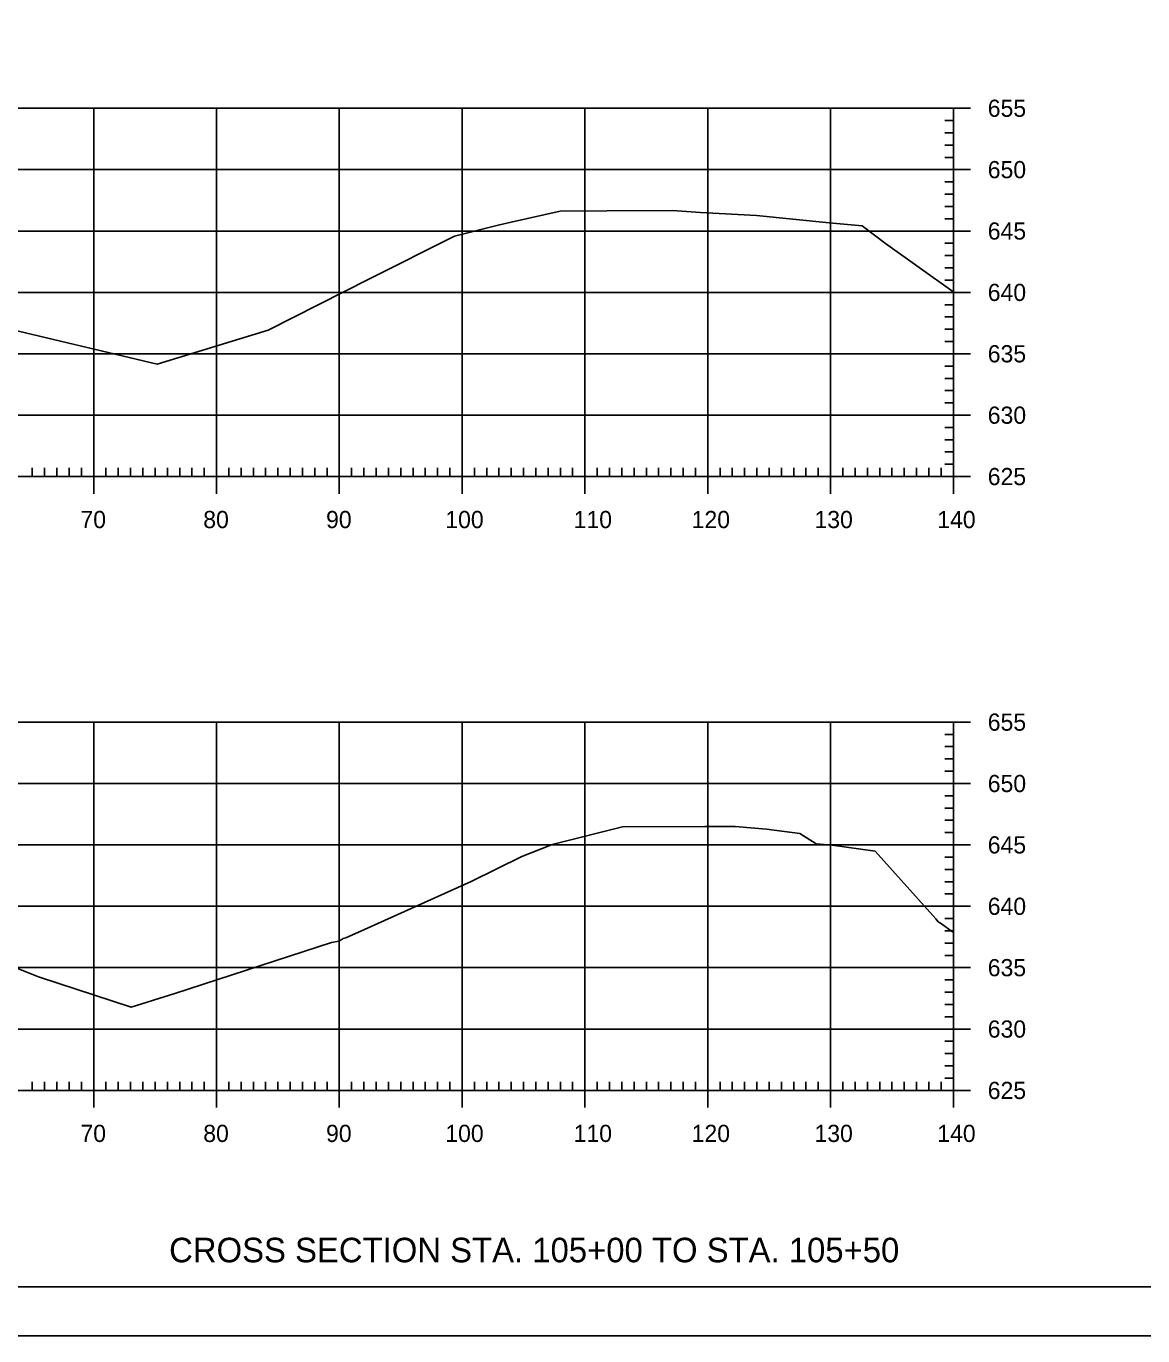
# Model space of a CAD drawing. Extents: x 1381471 to 1382703, y 370300 to 371487.
# Drawn here: x 1382201.1 to 1382292, y 371273.8 to 371380.5 of the extents above; entities that cross this region are included whole.
import ezdxf

# ---------------------------------------------------------------- set-up
doc = ezdxf.new("R2010")
doc.units = 0
doc.layers.add('Level 45', color=7, linetype='Continuous')

msp = doc.modelspace()

# ---------------------------------------------------------------- linework, layer by layer
at = {"layer": 'Level 45'}
for p, q in [((1381996.61, 371373.8), (1382276.61, 371373.8)), ((1382206.61, 371343.8), (1382206.61, 371373.8)), ((1382216.61, 371343.8), (1382216.61, 371373.8)), ((1382226.61, 371343.8), (1382226.61, 371373.8)), ((1382236.61, 371343.8), (1382236.61, 371373.8)), ((1382246.61, 371343.8), (1382246.61, 371373.8)), ((1382256.61, 371343.8), (1382256.61, 371373.8)), ((1382266.61, 371343.8), (1382266.61, 371373.8)), ((1382278.01, 371373.8), (1382275.21, 371373.8)), ((1382276.61, 371372.8), (1382275.91, 371372.8)), ((1382276.61, 371343.8), (1382276.61, 371373.8)), ((1382276.61, 371343.8), (1382276.61, 371373.8)), ((1382276.61, 371371.8), (1382275.91, 371371.8)), ((1382276.61, 371370.8), (1382275.91, 371370.8)), ((1382276.61, 371369.8), (1382275.91, 371369.8)), ((1381996.61, 371368.8), (1382276.61, 371368.8)), ((1382278.01, 371368.8), (1382275.21, 371368.8)), ((1382276.61, 371367.8), (1382275.91, 371367.8)), ((1382276.61, 371366.8), (1382275.91, 371366.8)), ((1382276.61, 371365.8), (1382275.91, 371365.8)), ((1382276.61, 371364.8), (1382275.91, 371364.8)), ((1381996.61, 371363.8), (1382276.61, 371363.8)), ((1382278.01, 371363.8), (1382275.21, 371363.8)), ((1382276.61, 371362.8), (1382275.91, 371362.8)), ((1382276.61, 371361.8), (1382275.91, 371361.8)), ((1382276.61, 371360.8), (1382275.91, 371360.8)), ((1382276.61, 371359.8), (1382275.91, 371359.8)), ((1381996.61, 371358.8), (1382276.61, 371358.8)), ((1382278.01, 371358.8), (1382275.21, 371358.8)), ((1382276.61, 371357.8), (1382275.91, 371357.8)), ((1382276.61, 371356.8), (1382275.91, 371356.8)), ((1382276.61, 371355.8), (1382275.91, 371355.8)), ((1382276.61, 371354.8), (1382275.91, 371354.8)), ((1381996.61, 371353.8), (1382276.61, 371353.8)), ((1382278.01, 371353.8), (1382275.21, 371353.8)), ((1382276.61, 371352.8), (1382275.91, 371352.8)), ((1382276.61, 371351.8), (1382275.91, 371351.8)), ((1382276.61, 371350.8), (1382275.91, 371350.8)), ((1382276.61, 371349.8), (1382275.91, 371349.8)), ((1381996.61, 371348.8), (1382276.61, 371348.8)), ((1382278.01, 371348.8), (1382275.21, 371348.8)), ((1382276.61, 371347.8), (1382275.91, 371347.8)), ((1382276.61, 371346.8), (1382275.91, 371346.8)), ((1382206.61, 371342.4), (1382206.61, 371345.2)), ((1382216.61, 371342.4), (1382216.61, 371345.2)), ((1382226.61, 371342.4), (1382226.61, 371345.2)), ((1382236.61, 371342.4), (1382236.61, 371345.2)), ((1382246.61, 371342.4), (1382246.61, 371345.2)), ((1382256.61, 371342.4), (1382256.61, 371345.2)), ((1382266.61, 371342.4), (1382266.61, 371345.2)), ((1382276.61, 371345.8), (1382275.91, 371345.8)), ((1382276.61, 371342.4), (1382276.61, 371345.2)), ((1382201.61, 371343.8), (1382201.61, 371344.5)), ((1382202.61, 371343.8), (1382202.61, 371344.5)), ((1382203.61, 371343.8), (1382203.61, 371344.5)), ((1382204.61, 371343.8), (1382204.61, 371344.5)), ((1382205.61, 371343.8), (1382205.61, 371344.5)), ((1382207.61, 371343.8), (1382207.61, 371344.5)), ((1382208.61, 371343.8), (1382208.61, 371344.5)), ((1382209.61, 371343.8), (1382209.61, 371344.5)), ((1382210.61, 371343.8), (1382210.61, 371344.5)), ((1382211.61, 371343.8), (1382211.61, 371344.5)), ((1382212.61, 371343.8), (1382212.61, 371344.5)), ((1382213.61, 371343.8), (1382213.61, 371344.5)), ((1382214.61, 371343.8), (1382214.61, 371344.5)), ((1382215.61, 371343.8), (1382215.61, 371344.5)), ((1382217.61, 371343.8), (1382217.61, 371344.5)), ((1382218.61, 371343.8), (1382218.61, 371344.5)), ((1382219.61, 371343.8), (1382219.61, 371344.5)), ((1382220.61, 371343.8), (1382220.61, 371344.5)), ((1382221.61, 371343.8), (1382221.61, 371344.5)), ((1382222.61, 371343.8), (1382222.61, 371344.5)), ((1382223.61, 371343.8), (1382223.61, 371344.5)), ((1382224.61, 371343.8), (1382224.61, 371344.5)), ((1382225.61, 371343.8), (1382225.61, 371344.5)), ((1382227.61, 371343.8), (1382227.61, 371344.5)), ((1382228.61, 371343.8), (1382228.61, 371344.5)), ((1382229.61, 371343.8), (1382229.61, 371344.5)), ((1382230.61, 371343.8), (1382230.61, 371344.5)), ((1382231.61, 371343.8), (1382231.61, 371344.5)), ((1382232.61, 371343.8), (1382232.61, 371344.5)), ((1382233.61, 371343.8), (1382233.61, 371344.5)), ((1382234.61, 371343.8), (1382234.61, 371344.5)), ((1382235.61, 371343.8), (1382235.61, 371344.5)), ((1382237.61, 371343.8), (1382237.61, 371344.5)), ((1382238.61, 371343.8), (1382238.61, 371344.5)), ((1382239.61, 371343.8), (1382239.61, 371344.5)), ((1382240.61, 371343.8), (1382240.61, 371344.5)), ((1382241.61, 371343.8), (1382241.61, 371344.5)), ((1382242.61, 371343.8), (1382242.61, 371344.5)), ((1382243.61, 371343.8), (1382243.61, 371344.5)), ((1382244.61, 371343.8), (1382244.61, 371344.5)), ((1382245.61, 371343.8), (1382245.61, 371344.5)), ((1382247.61, 371343.8), (1382247.61, 371344.5)), ((1382248.61, 371343.8), (1382248.61, 371344.5)), ((1382249.61, 371343.8), (1382249.61, 371344.5)), ((1382250.61, 371343.8), (1382250.61, 371344.5)), ((1382251.61, 371343.8), (1382251.61, 371344.5)), ((1382252.61, 371343.8), (1382252.61, 371344.5)), ((1382253.61, 371343.8), (1382253.61, 371344.5)), ((1382254.61, 371343.8), (1382254.61, 371344.5)), ((1382255.61, 371343.8), (1382255.61, 371344.5)), ((1382257.61, 371343.8), (1382257.61, 371344.5)), ((1382258.61, 371343.8), (1382258.61, 371344.5)), ((1382259.61, 371343.8), (1382259.61, 371344.5)), ((1382260.61, 371343.8), (1382260.61, 371344.5)), ((1382261.61, 371343.8), (1382261.61, 371344.5)), ((1382262.61, 371343.8), (1382262.61, 371344.5)), ((1382263.61, 371343.8), (1382263.61, 371344.5)), ((1382264.61, 371343.8), (1382264.61, 371344.5)), ((1382265.61, 371343.8), (1382265.61, 371344.5)), ((1382267.61, 371343.8), (1382267.61, 371344.5)), ((1382268.61, 371343.8), (1382268.61, 371344.5)), ((1382269.61, 371343.8), (1382269.61, 371344.5)), ((1382270.61, 371343.8), (1382270.61, 371344.5)), ((1382271.61, 371343.8), (1382271.61, 371344.5)), ((1382272.61, 371343.8), (1382272.61, 371344.5)), ((1382273.61, 371343.8), (1382273.61, 371344.5)), ((1382274.61, 371343.8), (1382274.61, 371344.5)), ((1382275.61, 371343.8), (1382275.61, 371344.5)), ((1382276.61, 371344.8), (1382275.91, 371344.8)), ((1381996.61, 371343.8), (1382276.61, 371343.8)), ((1381996.61, 371343.8), (1382276.61, 371343.8)), ((1382278.01, 371343.8), (1382275.21, 371343.8)), ((1381996.61, 371323.8), (1382276.61, 371323.8)), ((1382206.61, 371293.8), (1382206.61, 371323.8)), ((1382216.61, 371293.8), (1382216.61, 371323.8)), ((1382226.61, 371293.8), (1382226.61, 371323.8)), ((1382236.61, 371293.8), (1382236.61, 371323.8)), ((1382246.61, 371293.8), (1382246.61, 371323.8)), ((1382256.61, 371293.8), (1382256.61, 371323.8)), ((1382266.61, 371293.8), (1382266.61, 371323.8)), ((1382278.01, 371323.8), (1382275.21, 371323.8)), ((1382276.61, 371293.8), (1382276.61, 371323.8)), ((1382276.61, 371293.8), (1382276.61, 371323.8)), ((1382276.61, 371322.8), (1382275.91, 371322.8)), ((1382276.61, 371321.8), (1382275.91, 371321.8)), ((1382276.61, 371320.8), (1382275.91, 371320.8)), ((1382276.61, 371319.8), (1382275.91, 371319.8)), ((1381996.61, 371318.8), (1382276.61, 371318.8)), ((1382278.01, 371318.8), (1382275.21, 371318.8)), ((1382276.61, 371317.8), (1382275.91, 371317.8)), ((1382276.61, 371316.8), (1382275.91, 371316.8)), ((1382276.61, 371315.8), (1382275.91, 371315.8)), ((1382276.61, 371314.8), (1382275.91, 371314.8)), ((1381996.61, 371313.8), (1382276.61, 371313.8)), ((1382278.01, 371313.8), (1382275.21, 371313.8)), ((1382276.61, 371312.8), (1382275.91, 371312.8)), ((1382276.61, 371311.8), (1382275.91, 371311.8)), ((1382276.61, 371310.8), (1382275.91, 371310.8)), ((1381996.61, 371308.8), (1382276.61, 371308.8)), ((1382278.01, 371308.8), (1382275.21, 371308.8)), ((1382276.61, 371309.8), (1382275.91, 371309.8)), ((1382276.61, 371307.8), (1382275.91, 371307.8)), ((1382276.61, 371306.8), (1382275.91, 371306.8)), ((1382276.61, 371305.8), (1382275.91, 371305.8)), ((1382276.61, 371304.8), (1382275.91, 371304.8)), ((1381996.61, 371303.8), (1382276.61, 371303.8)), ((1382278.01, 371303.8), (1382275.21, 371303.8)), ((1382276.61, 371302.8), (1382275.91, 371302.8)), ((1382276.61, 371301.8), (1382275.91, 371301.8)), ((1382276.61, 371300.8), (1382275.91, 371300.8)), ((1382276.61, 371299.8), (1382275.91, 371299.8)), ((1381996.61, 371298.8), (1382276.61, 371298.8)), ((1382278.01, 371298.8), (1382275.21, 371298.8)), ((1382276.61, 371297.8), (1382275.91, 371297.8)), ((1382276.61, 371296.8), (1382275.91, 371296.8)), ((1382206.61, 371292.4), (1382206.61, 371295.2)), ((1382216.61, 371292.4), (1382216.61, 371295.2)), ((1382226.61, 371292.4), (1382226.61, 371295.2)), ((1382236.61, 371292.4), (1382236.61, 371295.2)), ((1382246.61, 371292.4), (1382246.61, 371295.2)), ((1382256.61, 371292.4), (1382256.61, 371295.2)), ((1382266.61, 371292.4), (1382266.61, 371295.2)), ((1382276.61, 371295.8), (1382275.91, 371295.8)), ((1382276.61, 371292.4), (1382276.61, 371295.2)), ((1382201.61, 371293.8), (1382201.61, 371294.5)), ((1382202.61, 371293.8), (1382202.61, 371294.5)), ((1382203.61, 371293.8), (1382203.61, 371294.5)), ((1382204.61, 371293.8), (1382204.61, 371294.5)), ((1382205.61, 371293.8), (1382205.61, 371294.5)), ((1382207.61, 371293.8), (1382207.61, 371294.5)), ((1382208.61, 371293.8), (1382208.61, 371294.5)), ((1382209.61, 371293.8), (1382209.61, 371294.5)), ((1382210.61, 371293.8), (1382210.61, 371294.5)), ((1382211.61, 371293.8), (1382211.61, 371294.5)), ((1382212.61, 371293.8), (1382212.61, 371294.5)), ((1382213.61, 371293.8), (1382213.61, 371294.5)), ((1382214.61, 371293.8), (1382214.61, 371294.5)), ((1382215.61, 371293.8), (1382215.61, 371294.5)), ((1382217.61, 371293.8), (1382217.61, 371294.5)), ((1382218.61, 371293.8), (1382218.61, 371294.5)), ((1382219.61, 371293.8), (1382219.61, 371294.5)), ((1382220.61, 371293.8), (1382220.61, 371294.5)), ((1382221.61, 371293.8), (1382221.61, 371294.5)), ((1382222.61, 371293.8), (1382222.61, 371294.5)), ((1382223.61, 371293.8), (1382223.61, 371294.5)), ((1382224.61, 371293.8), (1382224.61, 371294.5)), ((1382225.61, 371293.8), (1382225.61, 371294.5)), ((1382227.61, 371293.8), (1382227.61, 371294.5)), ((1382228.61, 371293.8), (1382228.61, 371294.5)), ((1382229.61, 371293.8), (1382229.61, 371294.5)), ((1382230.61, 371293.8), (1382230.61, 371294.5)), ((1382231.61, 371293.8), (1382231.61, 371294.5)), ((1382232.61, 371293.8), (1382232.61, 371294.5)), ((1382233.61, 371293.8), (1382233.61, 371294.5)), ((1382234.61, 371293.8), (1382234.61, 371294.5)), ((1382235.61, 371293.8), (1382235.61, 371294.5)), ((1382237.61, 371293.8), (1382237.61, 371294.5)), ((1382238.61, 371293.8), (1382238.61, 371294.5)), ((1382239.61, 371293.8), (1382239.61, 371294.5)), ((1382240.61, 371293.8), (1382240.61, 371294.5)), ((1382241.61, 371293.8), (1382241.61, 371294.5)), ((1382242.61, 371293.8), (1382242.61, 371294.5)), ((1382243.61, 371293.8), (1382243.61, 371294.5)), ((1382244.61, 371293.8), (1382244.61, 371294.5)), ((1382245.61, 371293.8), (1382245.61, 371294.5)), ((1382247.61, 371293.8), (1382247.61, 371294.5)), ((1382248.61, 371293.8), (1382248.61, 371294.5)), ((1382249.61, 371293.8), (1382249.61, 371294.5)), ((1382250.61, 371293.8), (1382250.61, 371294.5)), ((1382251.61, 371293.8), (1382251.61, 371294.5)), ((1382252.61, 371293.8), (1382252.61, 371294.5)), ((1382253.61, 371293.8), (1382253.61, 371294.5)), ((1382254.61, 371293.8), (1382254.61, 371294.5)), ((1382255.61, 371293.8), (1382255.61, 371294.5)), ((1382257.61, 371293.8), (1382257.61, 371294.5)), ((1382258.61, 371293.8), (1382258.61, 371294.5)), ((1382259.61, 371293.8), (1382259.61, 371294.5)), ((1382260.61, 371293.8), (1382260.61, 371294.5)), ((1382261.61, 371293.8), (1382261.61, 371294.5)), ((1382262.61, 371293.8), (1382262.61, 371294.5)), ((1382263.61, 371293.8), (1382263.61, 371294.5)), ((1382264.61, 371293.8), (1382264.61, 371294.5)), ((1382265.61, 371293.8), (1382265.61, 371294.5)), ((1382267.61, 371293.8), (1382267.61, 371294.5)), ((1382268.61, 371293.8), (1382268.61, 371294.5)), ((1382269.61, 371293.8), (1382269.61, 371294.5)), ((1382270.61, 371293.8), (1382270.61, 371294.5)), ((1382271.61, 371293.8), (1382271.61, 371294.5)), ((1382272.61, 371293.8), (1382272.61, 371294.5)), ((1382273.61, 371293.8), (1382273.61, 371294.5)), ((1382274.61, 371293.8), (1382274.61, 371294.5)), ((1382275.61, 371293.8), (1382275.61, 371294.5)), ((1382276.61, 371294.8), (1382275.91, 371294.8)), ((1381996.61, 371293.8), (1382276.61, 371293.8)), ((1381996.61, 371293.8), (1382276.61, 371293.8)), ((1382278.01, 371293.8), (1382275.21, 371293.8)), ((1382294.79, 371277.8), (1381978.61, 371277.8)), ((1381966.21, 371273.82), (1382299.55, 371273.82))]:
    msp.add_line(p, q, dxfattribs=at)
for points in [[(1381966.21, 371487.15), (1382299.55, 371487.15), (1382299.55, 371273.81), (1381966.21, 371273.81)], [(1382212.53, 371483.26), (1382232.15, 371483.26), (1382232.15, 371473.38), (1382248.27, 371473.38), (1382271.46, 371473.38), (1382271.46, 371449.04), (1382294.79, 371449.04), (1382294.79, 371277.8), (1381978.61, 371277.8), (1381978.61, 371483.26)]]:
    msp.add_lwpolyline(points, close=True, dxfattribs=at)
for points in [[(1382198.74, 371356.05), (1382211.78, 371352.96), (1382218.51, 371355.03), (1382220.81, 371355.73), (1382229.07, 371359.91), (1382235.99, 371363.39), (1382239.54, 371364.27), (1382240.59, 371364.51), (1382244.59, 371365.41), (1382248.4, 371365.43), (1382253.73, 371365.46), (1382256.02, 371365.32), (1382260.57, 371365.05), (1382266.51, 371364.47), (1382269.18, 371364.23), (1382271.08, 371362.79), (1382276.56, 371358.87), (1382276.61, 371358.83)], [(1382195.44, 371305.71), (1382202.11, 371303.06), (1382209.66, 371300.59), (1382213.22, 371301.69), (1382225.98, 371305.86), (1382226.61, 371305.96), (1382226.93, 371306.18), (1382227.14, 371306.22), (1382228.65, 371306.91), (1382237.35, 371310.83), (1382241.47, 371312.85), (1382243.88, 371313.8), (1382243.99, 371313.84), (1382244.06, 371313.86), (1382249.66, 371315.26), (1382256.37, 371315.29), (1382258.85, 371315.29), (1382261.39, 371315.07), (1382264.11, 371314.73), (1382265.44, 371313.89), (1382266.73, 371313.78), (1382270.23, 371313.29), (1382275.19, 371307.78), (1382275.38, 371307.53), (1382275.55, 371307.43), (1382276.61, 371306.65)]]:
    msp.add_lwpolyline(points, dxfattribs=at)

# ---------------------------------------------------------------- texts
for s, height, p in [('655', 1.4, (1382279.41, 371373.1)), ('650', 1.4, (1382279.41, 371368.1)), ('645', 1.4, (1382279.41, 371363.1)), ('640', 1.4, (1382279.41, 371358.1)), ('635', 1.4, (1382279.41, 371353.1)), ('630', 1.4, (1382279.41, 371348.1)), ('625', 1.4, (1382279.41, 371343.1)), ('70', 1.4, (1382205.53, 371339.6)), ('80', 1.4, (1382215.53, 371339.6)), ('90', 1.4, (1382225.53, 371339.6)), ('100', 1.4, (1382235.24, 371339.6)), ('110', 1.4, (1382245.69, 371339.6)), ('120', 1.4, (1382255.3, 371339.6)), ('130', 1.4, (1382265.3, 371339.6)), ('140', 1.4, (1382275.3, 371339.6)), ('655', 1.4, (1382279.41, 371323.1)), ('650', 1.4, (1382279.41, 371318.1)), ('645', 1.4, (1382279.41, 371313.1)), ('640', 1.4, (1382279.41, 371308.1)), ('635', 1.4, (1382279.41, 371303.1)), ('630', 1.4, (1382279.41, 371298.1)), ('625', 1.4, (1382279.41, 371293.1)), ('70', 1.4, (1382205.53, 371289.6)), ('80', 1.4, (1382215.53, 371289.6)), ('90', 1.4, (1382225.53, 371289.6)), ('100', 1.4, (1382235.24, 371289.6)), ('110', 1.4, (1382245.69, 371289.6)), ('120', 1.4, (1382255.3, 371289.6)), ('130', 1.4, (1382265.3, 371289.6)), ('140', 1.4, (1382275.3, 371289.6)), ('CROSS SECTION STA. 105+00 TO STA. 105+50', 2, (1382212.75, 371279.8))]:
    msp.add_text(s, height=height, dxfattribs=at).set_placement(p)

doc.saveas('drawing.dxf')
